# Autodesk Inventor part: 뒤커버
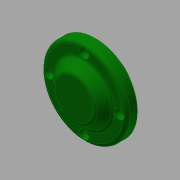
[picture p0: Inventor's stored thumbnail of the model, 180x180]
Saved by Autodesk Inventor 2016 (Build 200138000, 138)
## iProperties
Created: 2017-08
Part Number: 뒤커버
Material: 알루미늄 6061
Document SubType Name: Modeling
Designer: mduedu
Density: 1 g/cm^3
Appearance: 진녹색
Author: mduedu
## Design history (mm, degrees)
sketch "스케치1"
  geometry: C1 r 35 at (0, 0); 1 further point
  constraints: 1 centre point, 1 coincident
  dimensions: "d0" = 70 diameter of C1
extrude "돌출1" new body sketch "스케치1" distance "d1" = 10; taper "d2" = 0 deg
sketch "스케치2"
  geometry: C1 r 24 at (0, 0); 1 further point
  constraints: 1 centre point, 1 coincident
  dimensions: "d3" = 48 diameter of C1
node "작업 평면1"
sketch "스케치3"
  geometry: C1 r 17 at (0, 0); 1 further point
  constraints: 1 centre point, 1 coincident
  dimensions: "d5" = 34 diameter of C1
feature "로프트1" sketch "스케치3" dims "d6" = 0, "d7" = 90 deg, "d8" = 0, "d9" = 90 deg
sketch "스케치4"
  geometry: C1 r 24 at (0, 0) reference; 1 further point
extrude "돌출2" join sketch "스케치4" distance "d10" = 8; taper "d11" = 0 deg
hole "구멍1" diameter "d14" = 40; stored, may be unused: countersink angle "d18" = 90 deg, drill point angle "d20" = 0 deg; dims "d12" = 10, "d13" = 10, "d15" = 6, "d16" = 4, "d17" = 2, "d19" = 12
hole "구멍2" diameter "d23" = 34; stored, may be unused: countersink angle "d27" = 90 deg, drill point angle "d29" = 0 deg; dims "d24" = 6, "d25" = 4, "d26" = 2, "d28" = 6, "d62" = 10, "d63" = 10
chamfer "모따기1" distance "d39" = 1; stored, may be unused: second distance "d40" = 2, angle "d41" = 45 deg
fillet "모깎기1" dims "d42" = 0.3
fillet "모깎기2" dims "d43" = 3
sketch "스케치5" dims "d44" = 58
  geometry: 6 further points
  constraints: 2 vertical alignment, 1 coincident, 7 other
  dimensions: "d47" = 360 deg dimension on point (0, 0) point (0, 29) (derived)
sketch "스케치6"
  geometry: 4 further points
  constraints: 4 other
hole "구멍4" sketch "스케치6" at (0, 29), (-29, 0), (29, 0), (0, -29) diameter "d49" = 4.5; stored, may be unused: countersink angle "d53" = 90 deg, drill point angle "d55" = 0 deg; dims "d50" = 6, "d51" = 8, "d52" = 4.6, "d54" = 8
fillet "모깎기3" dims "d56" = 3
fillet "모깎기4" dims "d57" = 3
fillet "모깎기5" dims "d58" = 3
chamfer "모따기2" distance "d59" = 1; stored, may be unused: second distance "d60" = 2, angle "d61" = 45 deg
node "솔리드1"
other parameters: "d4" = 8
